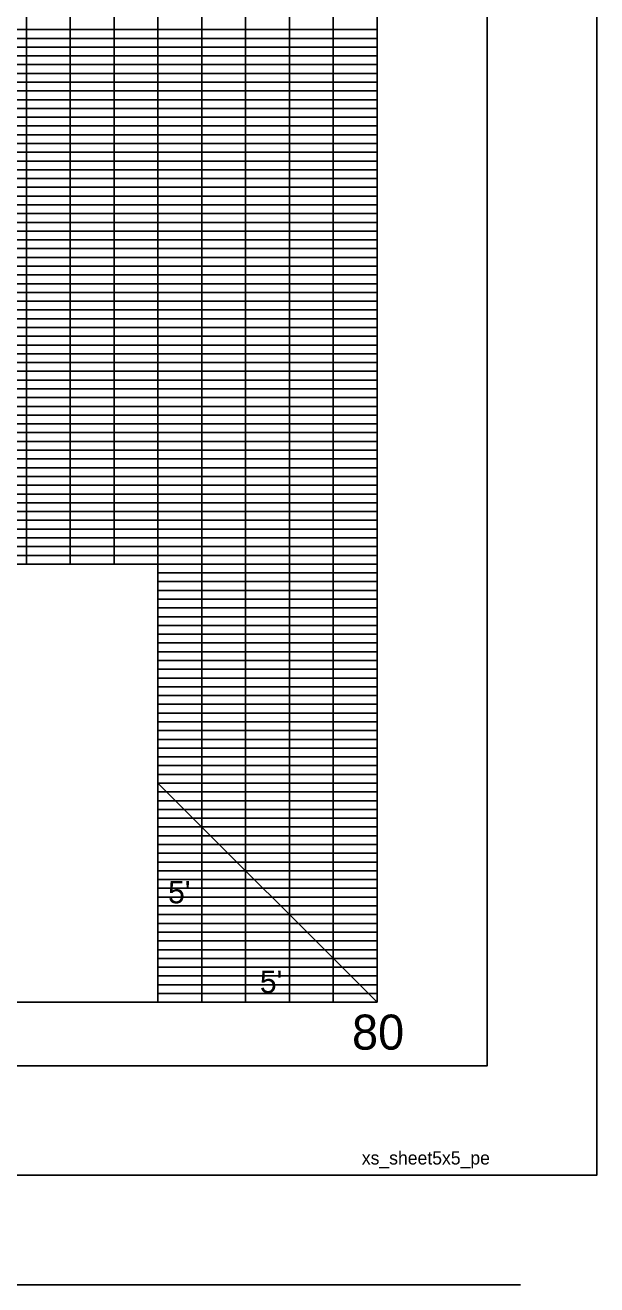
# Model space of a CAD drawing. Extents: x -15 to 165, y -6 to 109.
# Drawn here: x 151.97 to 165.01, y -6.45 to 22.3 of the extents above; entities that cross this region are included whole.
import ezdxf

# ---------------------------------------------------------------- set-up
doc = ezdxf.new("R2010")
doc.units = 0
for name, color, linetype in [('RD_SHT_Bndy', 7, 'Continuous'), ('RD_SHT_IplotShp', 7, 'Continuous'), ('RD_SHT_MjGrid', 7, 'Continuous'), ('RD_SHT_MnGrid', 7, 'Continuous'), ('RD_SHT_SubGrid', 7, 'Continuous'), ('RD_SHT_TX', 7, 'Continuous')]:
    doc.layers.add(name, color=color, linetype=linetype)

msp = doc.modelspace()

# ---------------------------------------------------------------- linework, layer by layer
at = {"layer": 'RD_SHT_Bndy'}
for p, q in [((155, 5), (160, 0)), ((-12.73, -3.949), (163.27, -3.949)), ((-12.73, -6.449), (163.27, -6.449))]:
    msp.add_line(p, q, dxfattribs=at)
msp.add_lwpolyline([(-4.99, 103.551), (162.51, 103.551), (162.51, -1.449), (-4.99, -1.449)], close=True, dxfattribs=at)
at = {"layer": 'RD_SHT_IplotShp'}
msp.add_lwpolyline([(-14.589, 106.051), (165.01, 106.051), (165.01, -3.949), (-14.589, -3.949)], close=True, dxfattribs=at)
at = {"layer": 'RD_SHT_MjGrid'}
for p, q in [((155, 0), (155, 100)), ((160, 0), (160, 100)), ((0, 20), (160, 20)), ((0, 15), (160, 15)), ((0, 10), (160, 10)), ((155, 5), (160, 5)), ((0, 0), (160, 0))]:
    msp.add_line(p, q, dxfattribs=at)
at = {"layer": 'RD_SHT_MnGrid'}
for p, q in [((152, 10), (152, 100)), ((153, 10), (153, 100)), ((154, 10), (154, 100)), ((156, 0), (156, 100)), ((157, 0), (157, 100)), ((158, 0), (158, 100)), ((159, 0), (159, 100)), ((0, 22), (160, 22)), ((0, 21), (160, 21)), ((0, 19), (160, 19)), ((0, 18), (160, 18)), ((0, 17), (160, 17)), ((0, 16), (160, 16)), ((0, 14), (160, 14)), ((0, 13), (160, 13)), ((0, 12), (160, 12)), ((0, 11), (160, 11)), ((155, 9), (160, 9)), ((155, 8), (160, 8)), ((155, 7), (160, 7)), ((155, 6), (160, 6)), ((155, 4), (160, 4)), ((155, 3), (160, 3)), ((155, 2), (160, 2)), ((155, 1), (160, 1))]:
    msp.add_line(p, q, dxfattribs=at)
at = {"layer": 'RD_SHT_SubGrid'}
for p, q in [((0, 22.2), (160, 22.2)), ((0, 21.8), (160, 21.8)), ((0, 21.6), (160, 21.6)), ((0, 21.4), (160, 21.4)), ((0, 21.2), (160, 21.2)), ((0, 20.8), (160, 20.8)), ((0, 20.6), (160, 20.6)), ((0, 20.4), (160, 20.4)), ((0, 20.2), (160, 20.2)), ((0, 19.8), (160, 19.8)), ((0, 19.6), (160, 19.6)), ((0, 19.4), (160, 19.4)), ((0, 19.2), (160, 19.2)), ((0, 18.8), (160, 18.8)), ((0, 18.6), (160, 18.6)), ((0, 18.4), (160, 18.4)), ((0, 18.2), (160, 18.2)), ((0, 17.8), (160, 17.8)), ((0, 17.6), (160, 17.6)), ((0, 17.4), (160, 17.4)), ((0, 17.2), (160, 17.2)), ((0, 16.8), (160, 16.8)), ((0, 16.6), (160, 16.6)), ((0, 16.4), (160, 16.4)), ((0, 16.2), (160, 16.2)), ((0, 15.8), (160, 15.8)), ((0, 15.6), (160, 15.6)), ((0, 15.4), (160, 15.4)), ((0, 15.2), (160, 15.2)), ((0, 14.8), (160, 14.8)), ((0, 14.6), (160, 14.6)), ((0, 14.4), (160, 14.4)), ((0, 14.2), (160, 14.2)), ((0, 13.8), (160, 13.8)), ((0, 13.6), (160, 13.6)), ((0, 13.4), (160, 13.4)), ((0, 13.2), (160, 13.2)), ((0, 12.8), (160, 12.8)), ((0, 12.6), (160, 12.6)), ((0, 12.4), (160, 12.4)), ((0, 12.2), (160, 12.2)), ((0, 11.8), (160, 11.8)), ((0, 11.6), (160, 11.6)), ((0, 11.4), (160, 11.4)), ((0, 11.2), (160, 11.2)), ((0, 10.8), (160, 10.8)), ((0, 10.6), (160, 10.6)), ((0, 10.4), (160, 10.4)), ((0, 10.2), (160, 10.2)), ((155, 9.8), (160, 9.8)), ((155, 9.6), (160, 9.6)), ((155, 9.4), (160, 9.4)), ((155, 9.2), (160, 9.2)), ((155, 8.8), (160, 8.8)), ((155, 8.6), (160, 8.6)), ((155, 8.4), (160, 8.4)), ((155, 8.2), (160, 8.2)), ((155, 7.8), (160, 7.8)), ((155, 7.6), (160, 7.6)), ((155, 7.4), (160, 7.4)), ((155, 7.2), (160, 7.2)), ((155, 6.8), (160, 6.8)), ((155, 6.6), (160, 6.6)), ((155, 6.4), (160, 6.4)), ((155, 6.2), (160, 6.2)), ((155, 5.8), (160, 5.8)), ((155, 5.6), (160, 5.6)), ((155, 5.4), (160, 5.4)), ((155, 5.2), (160, 5.2)), ((155, 5), (160, 5)), ((155, 4.8), (160, 4.8)), ((155, 4.6), (160, 4.6)), ((155, 4.4), (160, 4.4)), ((155, 4.2), (160, 4.2)), ((155, 3.8), (160, 3.8)), ((155, 3.6), (160, 3.6)), ((155, 3.4), (160, 3.4)), ((155, 3.2), (160, 3.2)), ((155, 2.8), (160, 2.8)), ((155, 2.6), (160, 2.6)), ((155, 2.4), (160, 2.4)), ((155, 2.2), (160, 2.2)), ((155, 1.8), (160, 1.8)), ((155, 1.6), (160, 1.6)), ((155, 1.4), (160, 1.4)), ((155, 1.2), (160, 1.2)), ((155, 0.8), (160, 0.8)), ((155, 0.6), (160, 0.6)), ((155, 0.4), (160, 0.4)), ((155, 0.2), (160, 0.2))]:
    msp.add_line(p, q, dxfattribs=at)

# ---------------------------------------------------------------- texts
at = {"layer": 'RD_SHT_TX'}
for s, height, p in [("5'", 0.512, (155.231, 2.258)), ("5'", 0.512, (157.325, 0.211)), ('80', 0.8, (159.426, -1.082)), ('xs_sheet5x5_pe', 0.3, (159.65, -3.704))]:
    msp.add_text(s, height=height, dxfattribs=at).set_placement(p)

doc.saveas('drawing.dxf')
